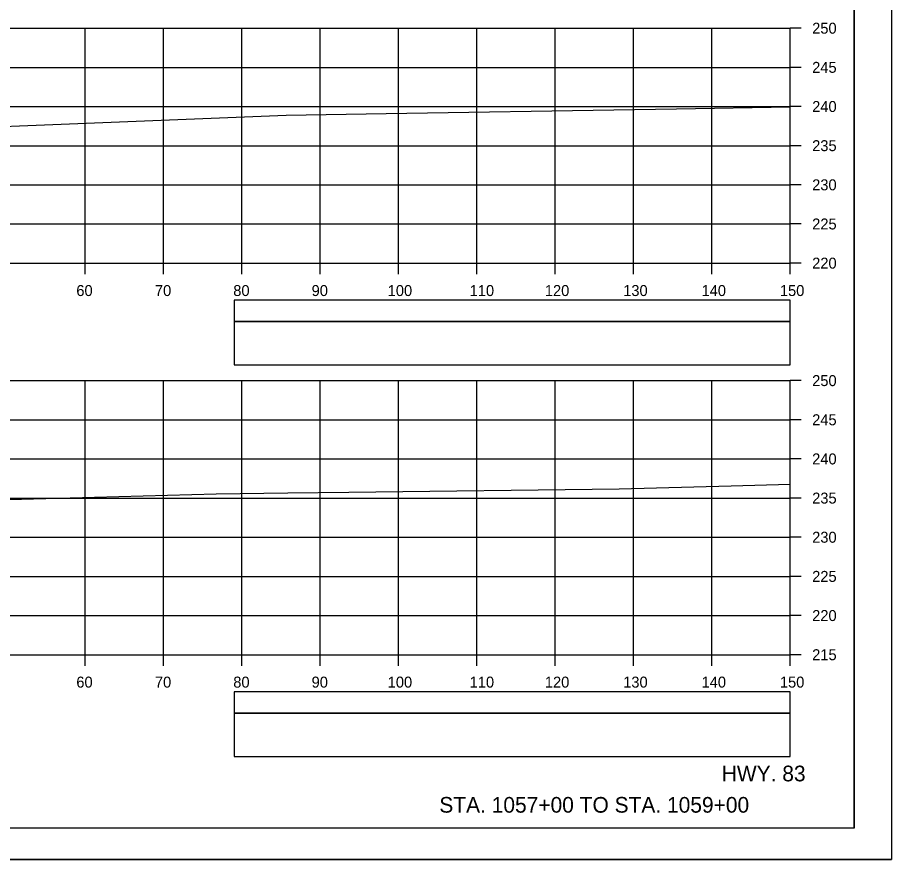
# Model space of a CAD drawing. Extents: x 1386544 to 1388153, y 379785 to 390999.
# Drawn here: x 1387411 to 1387522.6, y 388225.5 to 388333.1 of the extents above; entities that cross this region are included whole.
import ezdxf

# ---------------------------------------------------------------- set-up
doc = ezdxf.new("R2010")
doc.units = 0
for name, color, linetype in [('R_Axis', 7, 'Continuous'), ('R_Axis Annot', 7, 'Continuous'), ('R_Border', 7, 'Continuous'), ('R_Draft', 7, 'Continuous'), ('R_Exist Surface', 7, 'Continuous'), ('R_Grid', 7, 'Continuous'), ('R_No Plot', 7, 'Continuous')]:
    doc.layers.add(name, color=color, linetype=linetype)

msp = doc.modelspace()

# ---------------------------------------------------------------- linework, layer by layer
at = {"layer": 'R_Axis'}
for p, q in [((1387509.68, 388301.7), (1387509.68, 388331.7)), ((1387511.08, 388331.7), (1387509.68, 388331.7)), ((1387511.08, 388326.7), (1387509.68, 388326.7)), ((1387511.08, 388321.7), (1387509.68, 388321.7)), ((1387511.08, 388316.7), (1387509.68, 388316.7)), ((1387511.08, 388311.7), (1387509.68, 388311.7)), ((1387511.08, 388306.7), (1387509.68, 388306.7)), ((1387209.68, 388301.7), (1387509.68, 388301.7)), ((1387419.68, 388300.3), (1387419.68, 388301.7)), ((1387429.68, 388300.3), (1387429.68, 388301.7)), ((1387439.68, 388300.3), (1387439.68, 388301.7)), ((1387449.68, 388300.3), (1387449.68, 388301.7)), ((1387459.68, 388300.3), (1387459.68, 388301.7)), ((1387469.68, 388300.3), (1387469.68, 388301.7)), ((1387479.68, 388300.3), (1387479.68, 388301.7)), ((1387489.68, 388300.3), (1387489.68, 388301.7)), ((1387499.68, 388300.3), (1387499.68, 388301.7)), ((1387509.68, 388300.3), (1387509.68, 388301.7)), ((1387511.08, 388301.7), (1387509.68, 388301.7)), ((1387509.68, 388251.7), (1387509.68, 388286.7)), ((1387511.08, 388286.7), (1387509.68, 388286.7)), ((1387511.08, 388281.7), (1387509.68, 388281.7)), ((1387511.08, 388276.7), (1387509.68, 388276.7)), ((1387511.08, 388271.7), (1387509.68, 388271.7)), ((1387511.08, 388266.7), (1387509.68, 388266.7)), ((1387511.08, 388261.7), (1387509.68, 388261.7)), ((1387511.08, 388256.7), (1387509.68, 388256.7)), ((1387209.68, 388251.7), (1387509.68, 388251.7)), ((1387419.68, 388250.3), (1387419.68, 388251.7)), ((1387429.68, 388250.3), (1387429.68, 388251.7)), ((1387439.68, 388250.3), (1387439.68, 388251.7)), ((1387449.68, 388250.3), (1387449.68, 388251.7)), ((1387459.68, 388250.3), (1387459.68, 388251.7)), ((1387469.68, 388250.3), (1387469.68, 388251.7)), ((1387479.68, 388250.3), (1387479.68, 388251.7)), ((1387489.68, 388250.3), (1387489.68, 388251.7)), ((1387499.68, 388250.3), (1387499.68, 388251.7)), ((1387509.68, 388250.3), (1387509.68, 388251.7)), ((1387511.08, 388251.7), (1387509.68, 388251.7))]:
    msp.add_line(p, q, dxfattribs=at)
at = {"layer": 'R_Axis Annot'}
for points in [[(1387438.7, 388294.25), (1387509.68, 388294.25), (1387509.68, 388296.96), (1387438.7, 388296.96)], [(1387438.7, 388288.72), (1387509.68, 388288.72), (1387509.68, 388294.25), (1387438.7, 388294.25)], [(1387438.7, 388244.25), (1387509.68, 388244.25), (1387509.68, 388246.96), (1387438.7, 388246.96)], [(1387438.7, 388238.72), (1387509.68, 388238.72), (1387509.68, 388244.25), (1387438.7, 388244.25)]]:
    msp.add_lwpolyline(points, close=True, dxfattribs=at)
at = {"layer": 'R_Border'}
for q in [(1387517.86, 388434.99), (1387201.68, 388229.53)]:
    msp.add_line((1387517.86, 388229.53), q, dxfattribs=at)
at = {"layer": 'R_Exist Surface'}
for points in [[(1387209.68, 388312.44), (1387224.25, 388313.33), (1387231.43, 388313.77), (1387252.21, 388314.66), (1387256.62, 388314.8), (1387269.18, 388315.17), (1387302.11, 388316.19), (1387326.47, 388316.92), (1387352.15, 388317.64), (1387352.41, 388317.64), (1387356.95, 388317.77), (1387357.18, 388317.8), (1387400.46, 388318.9), (1387408.1, 388319.1), (1387412.36, 388319.28), (1387445.36, 388320.61), (1387458.1, 388320.8), (1387489.8, 388321.31), (1387495.17, 388321.41), (1387509.68, 388321.67)], [(1387209.68, 388263.9), (1387224.2, 388264.56), (1387239.93, 388265.32), (1387268.29, 388266.53), (1387285.58, 388267.51), (1387290.13, 388267.78), (1387317.67, 388268.7), (1387328.81, 388269.07), (1387330.58, 388269.13), (1387333.23, 388269.21), (1387359.38, 388270.02), (1387377.41, 388270.59), (1387389.77, 388270.95), (1387436.39, 388272.24), (1387445.54, 388272.36), (1387453.33, 388272.45), (1387487.86, 388272.87), (1387502.16, 388273.26), (1387509.68, 388273.48)]]:
    msp.add_lwpolyline(points, dxfattribs=at)
at = {"layer": 'R_Grid'}
for p, q in [((1387209.68, 388331.7), (1387509.68, 388331.7)), ((1387419.68, 388301.7), (1387419.68, 388331.7)), ((1387429.68, 388301.7), (1387429.68, 388331.7)), ((1387439.68, 388301.7), (1387439.68, 388331.7)), ((1387449.68, 388301.7), (1387449.68, 388331.7)), ((1387459.68, 388301.7), (1387459.68, 388331.7)), ((1387469.68, 388301.7), (1387469.68, 388331.7)), ((1387479.68, 388301.7), (1387479.68, 388331.7)), ((1387489.68, 388301.7), (1387489.68, 388331.7)), ((1387499.68, 388301.7), (1387499.68, 388331.7)), ((1387509.68, 388301.7), (1387509.68, 388331.7)), ((1387209.68, 388326.7), (1387509.68, 388326.7)), ((1387209.68, 388321.7), (1387509.68, 388321.7)), ((1387209.68, 388316.7), (1387509.68, 388316.7)), ((1387209.68, 388311.7), (1387509.68, 388311.7)), ((1387209.68, 388306.7), (1387509.68, 388306.7)), ((1387209.68, 388301.7), (1387509.68, 388301.7)), ((1387209.68, 388286.7), (1387509.68, 388286.7)), ((1387419.68, 388251.7), (1387419.68, 388286.7)), ((1387429.68, 388251.7), (1387429.68, 388286.7)), ((1387439.68, 388251.7), (1387439.68, 388286.7)), ((1387449.68, 388251.7), (1387449.68, 388286.7)), ((1387459.68, 388251.7), (1387459.68, 388286.7)), ((1387469.68, 388251.7), (1387469.68, 388286.7)), ((1387479.68, 388251.7), (1387479.68, 388286.7)), ((1387489.68, 388251.7), (1387489.68, 388286.7)), ((1387499.68, 388251.7), (1387499.68, 388286.7)), ((1387509.68, 388251.7), (1387509.68, 388286.7)), ((1387209.68, 388281.7), (1387509.68, 388281.7)), ((1387209.68, 388276.7), (1387509.68, 388276.7)), ((1387209.68, 388271.7), (1387509.68, 388271.7)), ((1387209.68, 388266.7), (1387509.68, 388266.7)), ((1387209.68, 388261.7), (1387509.68, 388261.7)), ((1387209.68, 388256.7), (1387509.68, 388256.7)), ((1387209.68, 388251.7), (1387509.68, 388251.7))]:
    msp.add_line(p, q, dxfattribs=at)
at = {"layer": 'R_No Plot'}
msp.add_line((1387189.28, 388225.55), (1387522.61, 388225.55), dxfattribs=at)
for points in [[(1387189.27, 388438.88), (1387522.61, 388438.88), (1387522.61, 388225.55), (1387189.27, 388225.55)], [(1387435.6, 388434.99), (1387455.22, 388434.99), (1387455.22, 388425.11), (1387471.33, 388425.11), (1387494.53, 388425.11), (1387494.53, 388400.78), (1387517.86, 388400.78), (1387517.86, 388229.53), (1387201.68, 388229.53), (1387201.68, 388434.99)]]:
    msp.add_lwpolyline(points, close=True, dxfattribs=at)

# ---------------------------------------------------------------- texts
at = {"layer": 'R_Axis Annot'}
for s, p in [('250', (1387512.48, 388331)), ('245', (1387512.48, 388326)), ('240', (1387512.48, 388321)), ('235', (1387512.48, 388316)), ('230', (1387512.48, 388311)), ('225', (1387512.48, 388306)), ('220', (1387512.48, 388301)), ('60', (1387418.56, 388297.5)), ('70', (1387428.59, 388297.5)), ('80', (1387438.59, 388297.5)), ('90', (1387448.59, 388297.5)), ('100', (1387458.3, 388297.5)), ('110', (1387468.76, 388297.5)), ('120', (1387478.36, 388297.5)), ('130', (1387488.36, 388297.5)), ('140', (1387498.36, 388297.5)), ('150', (1387508.36, 388297.5)), ('250', (1387512.48, 388286)), ('245', (1387512.48, 388281)), ('240', (1387512.48, 388276)), ('235', (1387512.48, 388271)), ('230', (1387512.48, 388266)), ('225', (1387512.48, 388261)), ('220', (1387512.48, 388256)), ('215', (1387512.48, 388251)), ('60', (1387418.56, 388247.5)), ('70', (1387428.59, 388247.5)), ('80', (1387438.59, 388247.5)), ('90', (1387448.59, 388247.5)), ('100', (1387458.3, 388247.5)), ('110', (1387468.76, 388247.5)), ('120', (1387478.36, 388247.5)), ('130', (1387488.36, 388247.5)), ('140', (1387498.36, 388247.5)), ('150', (1387508.36, 388247.5))]:
    msp.add_text(s, height=1.4, dxfattribs=at).set_placement(p)
at = {"layer": 'R_Draft'}
for s, p in [('HWY. 83', (1387500.94, 388235.53)), ('STA. 1057+00 TO STA. 1059+00', (1387464.89, 388231.53))]:
    msp.add_text(s, height=2, dxfattribs=at).set_placement(p)

doc.saveas('drawing.dxf')
